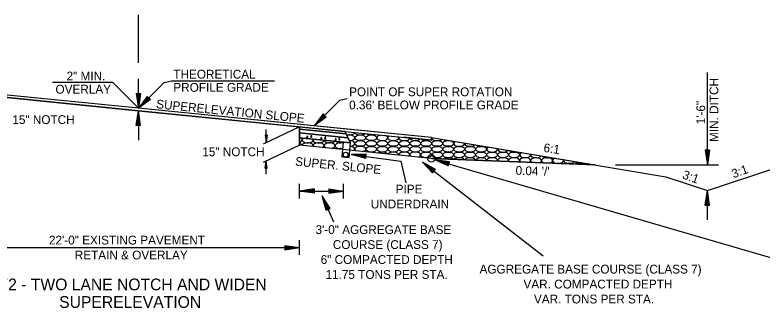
# Model space of a CAD drawing. Extents: x 1371763 to 1372860, y 385599 to 385872.
# Drawn here: x 1372551.5 to 1372602.5, y 385653.6 to 385673.6 of the extents above; entities that cross this region are included whole.
import ezdxf

# ---------------------------------------------------------------- set-up
doc = ezdxf.new("R2010")
doc.units = 0
doc.layers.add('R_Draft', color=7, linetype='Continuous')
doc.layers.add('R_Fin Surface', color=7, linetype='Continuous')

msp = doc.modelspace()

# ---------------------------------------------------------------- linework, layer by layer
at = {"layer": 'R_Draft'}
for p, q in [((1372559.921, 385670.294), (1372559.92, 385673.56)), ((1372598.764, 385663.329), (1372598.764, 385669.627)), ((1372558.173, 385668.943), (1372554.047, 385668.943)), ((1372559.923, 385667.193), (1372558.173, 385668.943)), ((1372559.923, 385667.193), (1372559.923, 385669.193)), ((1372559.923, 385667.193), (1372561.673, 385668.943)), ((1372561.673, 385668.943), (1372562.173, 385669.068)), ((1372562.173, 385669.068), (1372569.212, 385669.068)), ((1372559.923, 385667.026), (1372545.841, 385668.434)), ((1372559.923, 385667.193), (1372547.923, 385668.393)), ((1372559.773, 385668.193), (1372559.923, 385667.193)), ((1372559.773, 385668.193), (1372560.073, 385668.193)), ((1372559.798, 385668.193), (1372559.923, 385667.36)), ((1372559.823, 385668.193), (1372559.923, 385667.532)), ((1372559.848, 385668.193), (1372559.923, 385667.698)), ((1372559.874, 385668.193), (1372559.923, 385667.868)), ((1372559.899, 385668.193), (1372559.923, 385668.035)), ((1372560.073, 385668.193), (1372559.923, 385667.193)), ((1372559.972, 385668.193), (1372559.923, 385667.868)), ((1372560.022, 385668.193), (1372559.923, 385667.532)), ((1372560.048, 385668.193), (1372559.923, 385667.36)), ((1372559.997, 385668.193), (1372559.923, 385667.698)), ((1372559.946, 385668.193), (1372559.923, 385668.035)), ((1372560.524, 385668.006), (1372559.923, 385667.193)), ((1372560.541, 385667.988), (1372560.041, 385667.311)), ((1372560.56, 385667.97), (1372560.162, 385667.432)), ((1372560.577, 385667.952), (1372560.28, 385667.55)), ((1372560.595, 385667.934), (1372560.4, 385667.67)), ((1372560.664, 385667.865), (1372560.4, 385667.67)), ((1372560.613, 385667.916), (1372560.518, 385667.788)), ((1372560.646, 385667.883), (1372560.518, 385667.788)), ((1372560.736, 385667.794), (1372560.524, 385668.006)), ((1372573.673, 385667.743), (1372574.173, 385667.868)), ((1372560.736, 385667.794), (1372559.923, 385667.193)), ((1372560.718, 385667.811), (1372560.041, 385667.311)), ((1372560.7, 385667.829), (1372560.162, 385667.432)), ((1372560.683, 385667.847), (1372560.28, 385667.55)), ((1372571.923, 385665.993), (1372573.673, 385667.743)), ((1372559.773, 385666.026), (1372559.923, 385667.026)), ((1372559.798, 385666.026), (1372559.923, 385666.859)), ((1372571.923, 385665.993), (1372559.923, 385667.193)), ((1372560.073, 385666.026), (1372559.923, 385667.026)), ((1372559.923, 385667.026), (1372559.923, 385665.026)), ((1372560.048, 385666.026), (1372559.923, 385666.859)), ((1372559.823, 385666.026), (1372559.923, 385666.687)), ((1372559.848, 385666.026), (1372559.923, 385666.52)), ((1372559.874, 385666.026), (1372559.923, 385666.351)), ((1372560.022, 385666.026), (1372559.923, 385666.687)), ((1372559.997, 385666.026), (1372559.923, 385666.52)), ((1372559.971, 385666.026), (1372559.923, 385666.351)), ((1372572.524, 385666.806), (1372571.923, 385665.993)), ((1372572.736, 385666.594), (1372571.923, 385665.993)), ((1372572.541, 385666.788), (1372572.041, 385666.111)), ((1372572.718, 385666.611), (1372572.041, 385666.111)), ((1372572.56, 385666.77), (1372572.162, 385666.232)), ((1372572.7, 385666.629), (1372572.162, 385666.232)), ((1372572.577, 385666.752), (1372572.28, 385666.35)), ((1372572.683, 385666.647), (1372572.28, 385666.35)), ((1372572.595, 385666.734), (1372572.4, 385666.47)), ((1372572.664, 385666.665), (1372572.4, 385666.47)), ((1372572.613, 385666.716), (1372572.518, 385666.588)), ((1372572.646, 385666.683), (1372572.518, 385666.588)), ((1372572.736, 385666.594), (1372572.524, 385666.806)), ((1372560.073, 385666.026), (1372559.773, 385666.026)), ((1372559.899, 385666.026), (1372559.923, 385666.184)), ((1372559.946, 385666.026), (1372559.923, 385666.184)), ((1372570.921, 385665.926), (1372568.433, 385664.754)), ((1372579.918, 385665.193), (1372571.923, 385665.993)), ((1372568.571, 385665.354), (1372568.646, 385664.854)), ((1372568.721, 385665.354), (1372568.571, 385665.354)), ((1372568.583, 385665.354), (1372568.646, 385664.938)), ((1372568.596, 385665.354), (1372568.646, 385665.024)), ((1372568.609, 385665.354), (1372568.646, 385665.107)), ((1372568.621, 385665.354), (1372568.646, 385665.192)), ((1372568.634, 385665.354), (1372568.646, 385665.275)), ((1372568.646, 385664.854), (1372568.646, 385665.754)), ((1372568.721, 385665.354), (1372568.646, 385664.854)), ((1372568.67, 385665.354), (1372568.646, 385665.192)), ((1372568.696, 385665.354), (1372568.646, 385665.024)), ((1372568.708, 385665.354), (1372568.646, 385664.938)), ((1372568.683, 385665.354), (1372568.646, 385665.107)), ((1372568.658, 385665.354), (1372568.646, 385665.275)), ((1372574.096, 385665.442), (1372570.922, 385665.759)), ((1372574.228, 385665.179), (1372570.922, 385665.509)), ((1372574.009, 385665.617), (1372574.403, 385664.828)), ((1372574.403, 385664.828), (1372570.922, 385665.176)), ((1372579.918, 385665.026), (1372578.01, 385665.217)), ((1372579.918, 385665.193), (1372595.918, 385662.526)), ((1372579.918, 385665.193), (1372579.918, 385665.026)), ((1372570.921, 385664.676), (1372568.434, 385663.504)), ((1372579.918, 385663.776), (1372570.921, 385664.676)), ((1372598.614, 385664.329), (1372598.764, 385663.329)), ((1372598.914, 385664.329), (1372598.614, 385664.329)), ((1372598.639, 385664.329), (1372598.764, 385663.496)), ((1372598.665, 385664.329), (1372598.764, 385663.668)), ((1372598.69, 385664.329), (1372598.764, 385663.835)), ((1372598.715, 385664.329), (1372598.764, 385664.004)), ((1372598.741, 385664.329), (1372598.764, 385664.171)), ((1372598.914, 385664.329), (1372598.764, 385663.329)), ((1372598.813, 385664.329), (1372598.764, 385664.004)), ((1372598.864, 385664.329), (1372598.764, 385663.668)), ((1372598.889, 385664.329), (1372598.764, 385663.496)), ((1372598.839, 385664.329), (1372598.764, 385663.835)), ((1372598.788, 385664.329), (1372598.764, 385664.171)), ((1372575.478, 385664.057), (1372574.466, 385664.042)), ((1372574.466, 385664.042), (1372577.831, 385663.586)), ((1372575.437, 385663.759), (1372574.466, 385664.042)), ((1372575.474, 385664.032), (1372574.632, 385664.02)), ((1372575.441, 385663.784), (1372574.632, 385664.02)), ((1372575.471, 385664.007), (1372574.802, 385663.997)), ((1372575.444, 385663.809), (1372574.802, 385663.997)), ((1372575.467, 385663.982), (1372574.967, 385663.974)), ((1372575.447, 385663.834), (1372574.967, 385663.974)), ((1372575.464, 385663.957), (1372575.135, 385663.952)), ((1372575.451, 385663.86), (1372575.135, 385663.952)), ((1372575.461, 385663.931), (1372575.301, 385663.929)), ((1372575.454, 385663.885), (1372575.301, 385663.929)), ((1372575.437, 385663.759), (1372575.478, 385664.057)), ((1372579.918, 385663.776), (1372591.103, 385663.329)), ((1372579.918, 385663.776), (1372591.103, 385663.329)), ((1372568.571, 385663.104), (1372568.646, 385663.604)), ((1372568.584, 385663.104), (1372568.646, 385663.521)), ((1372568.597, 385663.104), (1372568.646, 385663.435)), ((1372568.609, 385663.104), (1372568.646, 385663.352)), ((1372568.622, 385663.104), (1372568.646, 385663.267)), ((1372568.721, 385663.104), (1372568.646, 385663.604)), ((1372568.646, 385662.704), (1372568.646, 385663.604)), ((1372568.709, 385663.104), (1372568.646, 385663.521)), ((1372568.696, 385663.104), (1372568.646, 385663.435)), ((1372568.684, 385663.104), (1372568.646, 385663.352)), ((1372568.671, 385663.104), (1372568.646, 385663.267)), ((1372577.831, 385663.586), (1372578.171, 385662.109)), ((1372580.007, 385662.782), (1372579.308, 385663.513)), ((1372580.191, 385663.019), (1372579.308, 385663.513)), ((1372579.308, 385663.513), (1372587.56, 385657.125)), ((1372580.022, 385662.802), (1372579.44, 385663.411)), ((1372580.175, 385663), (1372579.44, 385663.411)), ((1372580.16, 385662.979), (1372579.576, 385663.305)), ((1372580.038, 385662.822), (1372579.576, 385663.305)), ((1372581.069, 385663.261), (1372580.151, 385663.684)), ((1372581.153, 385663.549), (1372580.151, 385663.684)), ((1372580.151, 385663.684), (1372603.456, 385656.902)), ((1372581.076, 385663.285), (1372580.311, 385663.638)), ((1372581.146, 385663.525), (1372580.311, 385663.638)), ((1372581.139, 385663.5), (1372580.476, 385663.59)), ((1372581.083, 385663.309), (1372580.476, 385663.59)), ((1372581.09, 385663.333), (1372580.636, 385663.543)), ((1372581.132, 385663.476), (1372580.636, 385663.543)), ((1372581.125, 385663.452), (1372580.799, 385663.496)), ((1372581.097, 385663.358), (1372580.799, 385663.496)), ((1372581.118, 385663.428), (1372580.959, 385663.449)), ((1372581.104, 385663.382), (1372580.959, 385663.449)), ((1372581.069, 385663.261), (1372581.153, 385663.549)), ((1372592.486, 385663.329), (1372599.514, 385663.329)), ((1372568.571, 385663.104), (1372568.721, 385663.104)), ((1372568.635, 385663.104), (1372568.646, 385663.183)), ((1372568.658, 385663.104), (1372568.646, 385663.183)), ((1372580.053, 385662.842), (1372579.708, 385663.203)), ((1372580.145, 385662.96), (1372579.708, 385663.203)), ((1372580.129, 385662.94), (1372579.842, 385663.1)), ((1372580.069, 385662.862), (1372579.842, 385663.1)), ((1372580.113, 385662.919), (1372579.974, 385662.998)), ((1372580.085, 385662.882), (1372579.974, 385662.998)), ((1372580.007, 385662.782), (1372580.191, 385663.019)), ((1372570.923, 385661.044), (1372570.923, 385662.044)), ((1372573.923, 385661.044), (1372573.923, 385662.044)), ((1372571.923, 385661.694), (1372570.923, 385661.544)), ((1372571.923, 385661.394), (1372570.923, 385661.544)), ((1372570.923, 385661.544), (1372573.923, 385661.544)), ((1372571.923, 385661.669), (1372571.09, 385661.544)), ((1372571.923, 385661.419), (1372571.09, 385661.544)), ((1372571.923, 385661.644), (1372571.262, 385661.544)), ((1372571.923, 385661.445), (1372571.262, 385661.544)), ((1372571.923, 385661.619), (1372571.428, 385661.544)), ((1372571.923, 385661.47), (1372571.428, 385661.544)), ((1372571.923, 385661.593), (1372571.598, 385661.544)), ((1372571.923, 385661.495), (1372571.598, 385661.544)), ((1372571.923, 385661.568), (1372571.765, 385661.544)), ((1372571.923, 385661.521), (1372571.765, 385661.544)), ((1372571.923, 385661.694), (1372571.923, 385661.394)), ((1372572.923, 385661.694), (1372573.923, 385661.544)), ((1372572.923, 385661.694), (1372572.923, 385661.394)), ((1372572.923, 385661.669), (1372573.756, 385661.544)), ((1372572.923, 385661.644), (1372573.584, 385661.544)), ((1372572.923, 385661.619), (1372573.417, 385661.544)), ((1372572.923, 385661.593), (1372573.248, 385661.544)), ((1372572.923, 385661.568), (1372573.081, 385661.544)), ((1372572.923, 385661.394), (1372573.923, 385661.544)), ((1372572.923, 385661.495), (1372573.248, 385661.544)), ((1372572.923, 385661.445), (1372573.584, 385661.544)), ((1372572.923, 385661.419), (1372573.756, 385661.544)), ((1372572.923, 385661.47), (1372573.417, 385661.544)), ((1372572.923, 385661.521), (1372573.081, 385661.544)), ((1372598.614, 385660.578), (1372598.764, 385661.578)), ((1372598.639, 385660.578), (1372598.764, 385661.411)), ((1372598.665, 385660.578), (1372598.764, 385661.239)), ((1372598.914, 385660.578), (1372598.764, 385661.578)), ((1372598.764, 385659.578), (1372598.764, 385661.578)), ((1372598.889, 385660.578), (1372598.764, 385661.411)), ((1372598.864, 385660.578), (1372598.764, 385661.239)), ((1372572.733, 385660.236), (1372572.468, 385661.212)), ((1372573.007, 385660.356), (1372572.468, 385661.212)), ((1372572.468, 385661.212), (1372573.247, 385659.438)), ((1372572.756, 385660.246), (1372572.535, 385661.059)), ((1372572.984, 385660.346), (1372572.535, 385661.059)), ((1372572.961, 385660.336), (1372572.604, 385660.901)), ((1372572.779, 385660.256), (1372572.604, 385660.901)), ((1372572.802, 385660.266), (1372572.671, 385660.749)), ((1372572.938, 385660.326), (1372572.671, 385660.749)), ((1372598.69, 385660.578), (1372598.764, 385661.072)), ((1372598.716, 385660.578), (1372598.764, 385660.903)), ((1372598.741, 385660.578), (1372598.764, 385660.736)), ((1372598.839, 385660.578), (1372598.764, 385661.072)), ((1372598.813, 385660.578), (1372598.764, 385660.903)), ((1372598.788, 385660.578), (1372598.764, 385660.736)), ((1372572.733, 385660.236), (1372573.007, 385660.356)), ((1372572.915, 385660.316), (1372572.739, 385660.594)), ((1372572.826, 385660.277), (1372572.739, 385660.594)), ((1372572.891, 385660.306), (1372572.806, 385660.441)), ((1372572.848, 385660.287), (1372572.806, 385660.441)), ((1372598.614, 385660.578), (1372598.914, 385660.578)), ((1372570.921, 385657.191), (1372570.921, 385658.191)), ((1372548.921, 385657.691), (1372570.921, 385657.691)), ((1372569.921, 385657.841), (1372570.921, 385657.691)), ((1372569.921, 385657.841), (1372569.921, 385657.541)), ((1372569.921, 385657.816), (1372570.754, 385657.691)), ((1372569.921, 385657.79), (1372570.582, 385657.691)), ((1372569.921, 385657.765), (1372570.415, 385657.691)), ((1372569.921, 385657.739), (1372570.246, 385657.691)), ((1372569.921, 385657.714), (1372570.079, 385657.691)), ((1372569.921, 385657.541), (1372570.921, 385657.691)), ((1372569.921, 385657.642), (1372570.246, 385657.691)), ((1372569.921, 385657.591), (1372570.582, 385657.691)), ((1372569.921, 385657.566), (1372570.754, 385657.691)), ((1372569.921, 385657.616), (1372570.415, 385657.691)), ((1372569.921, 385657.667), (1372570.079, 385657.691))]:
    msp.add_line(p, q, dxfattribs=at)
for points in [[(1372559.923, 385667.193), (1372545.92, 385668.593), (1372539.919, 385669.193), (1372539.919, 385669.026), (1372545.841, 385668.434), (1372548.921, 385668.126), (1372559.923, 385667.026), (1372570.921, 385665.926), (1372574.009, 385665.617), (1372579.918, 385665.026), (1372579.92, 385665.193), (1372573.921, 385665.793)], [(1372570.921, 385665.926), (1372574.009, 385665.617), (1372574.096, 385665.442), (1372570.922, 385665.759)], [(1372579.918, 385663.776), (1372570.921, 385664.676), (1372570.922, 385665.176), (1372574.403, 385664.828), (1372574.228, 385665.179), (1372574.096, 385665.442), (1372574.009, 385665.617), (1372579.918, 385665.026), (1372579.918, 385665.193), (1372591.103, 385663.329)], [(1372570.922, 385665.509), (1372570.922, 385665.759), (1372574.096, 385665.442), (1372574.228, 385665.179)], [(1372570.922, 385665.509), (1372574.228, 385665.179), (1372574.403, 385664.828), (1372570.922, 385665.176)], [(1372573.902, 385664.878), (1372573.803, 385663.885), (1372574.304, 385663.835), (1372574.403, 385664.828)]]:
    msp.add_lwpolyline(points, close=True, dxfattribs=at)
for points in [[(1372574.009, 385665.617), (1372559.923, 385667.026)], [(1372570.921, 385665.926), (1372570.922, 385665.759), (1372570.922, 385665.509), (1372570.922, 385665.176), (1372570.921, 385664.676)], [(1372571.461, 385665.324), (1372571.398, 385665.198), (1372571.486, 385665.192), (1372571.461, 385665.324)], [(1372571.726, 385665.361), (1372571.663, 385665.234), (1372571.751, 385665.228), (1372571.726, 385665.361)], [(1372572.425, 385665.228), (1372572.362, 385665.101), (1372572.45, 385665.095), (1372572.425, 385665.228)], [(1372572.69, 385665.264), (1372572.627, 385665.138), (1372572.715, 385665.131), (1372572.69, 385665.264)], [(1372573.389, 385665.132), (1372573.326, 385665.005), (1372573.414, 385664.999), (1372573.389, 385665.132)], [(1372573.654, 385665.168), (1372573.591, 385665.041), (1372573.679, 385665.035), (1372573.654, 385665.168)]]:
    msp.add_lwpolyline(points, dxfattribs=at)
for centre, radius in [((1372574.07, 385664.026), 0.167), ((1372579.918, 385663.776), 0.25)]:
    msp.add_circle(centre, radius, dxfattribs=at)
for centre, start_param, end_param in [((1372574.315, 385665.568), 4.151582, 6.188458), ((1372574.315, 385665.179), 1.184818, 2.051954), ((1372574.315, 385665.179), 4.73799, 7.468004), ((1372575.065, 385665.568), 3.238092, 5.805198), ((1372575.816, 385665.568), 3.674985, 5.368305), ((1372576.566, 385665.179), 1.777481, 7.265809), ((1372577.316, 385665.179), 2.376985, 6.666305), ((1372570.719, 385664.637), 0.116474, 0.999932), ((1372570.719, 385665.025), 5.283453, 7.139386), ((1372571.469, 385665.025), 2.442518, 6.600772), ((1372571.469, 385664.637), 6.015594, 9.310881), ((1372572.219, 385664.637), 5.619002, 9.707473), ((1372572.219, 385665.025), 2.843099, 6.200191), ((1372572.97, 385664.637), 5.104074, 10.222401), ((1372572.97, 385665.025), 3.225943, 5.817347), ((1372573.72, 385664.637), 1.083587, 5.096112), ((1372573.72, 385665.025), 3.659508, 5.213681), ((1372574.315, 385664.791), 0.245719, 1.545025), ((1372574.315, 385664.791), 4.887187, 6.528905), ((1372578.067, 385665.179), 2.786407, 6.256883), ((1372578.817, 385665.179), 3.168029, 5.875261), ((1372579.567, 385665.179), 3.587687, 5.455603), ((1372579.567, 385665.179), 5.930026, 6.335044), ((1372580.317, 385665.179), 3.090586, 5.711462), ((1372581.068, 385665.179), 3.885721, 4.916327), ((1372581.818, 385664.791), 2.395711, 6.326095), ((1372582.568, 385664.791), 3.023167, 5.778882), ((1372581.818, 385664.791), 0.04291, 0.123152), ((1372573.72, 385664.248), 1.195019, 2.103665), ((1372574.315, 385664.402), 0.934459, 1.397587), ((1372574.315, 385664.402), 5.755866, 7.217645), ((1372575.065, 385664.402), 5.303745, 10.02273), ((1372583.318, 385664.791), 3.764994, 5.037054), ((1372584.069, 385664.402), 2.32197, 6.480078), ((1372584.819, 385664.402), 2.956625, 5.845423), ((1372585.569, 385664.402), 3.661482, 5.140566), ((1372575.816, 385664.014), 0.874925, 1.88518), ((1372576.566, 385664.014), 0.328166, 2.431939), ((1372577.316, 385664.014), 6.209463, 9.117012), ((1372578.067, 385664.014), 5.826908, 9.499567), ((1372578.817, 385664.014), 5.395855, 9.93062), ((1372579.567, 385663.625), 1.040624, 1.719481), ((1372580.317, 385663.625), 0.691764, 2.295662), ((1372581.068, 385663.625), 0.49489, 2.492535), ((1372581.818, 385663.625), 0.320594, 2.666831), ((1372582.568, 385663.625), 0.158349, 2.829076), ((1372583.318, 385663.625), 0.002249, 2.985176), ((1372584.069, 385663.625), 6.131267, 9.422529), ((1372584.819, 385663.625), 5.975278, 9.578518), ((1372585.569, 385663.625), 5.813283, 9.740513), ((1372586.319, 385664.014), 2.245061, 6.556988), ((1372586.319, 385663.625), 5.639452, 9.914344), ((1372587.07, 385663.625), 5.443475, 10.110321), ((1372587.07, 385664.014), 2.890642, 5.911406), ((1372587.82, 385663.625), 5.199841, 10.353956), ((1372587.82, 385664.014), 3.568612, 5.233436), ((1372588.57, 385663.625), 2.164004, 4.587381), ((1372588.57, 385663.625), 4.68323, 6.638044), ((1372588.57, 385663.236), 1.395788, 1.591637), ((1372589.321, 385663.625), 2.824922, 5.977126), ((1372589.321, 385663.236), 0.922405, 2.06502), ((1372590.071, 385663.625), 3.483025, 5.319023), ((1372590.071, 385663.236), 0.680517, 2.306909), ((1372590.821, 385663.236), 2.0774, 2.502171)]:
    msp.add_ellipse(centre, major_axis=(0.375, 0), ratio=0.517889, start_param=start_param, end_param=end_param, dxfattribs=at)
for centre in [(1372575.065, 385665.179), (1372575.816, 385665.179), (1372575.065, 385664.791), (1372575.816, 385664.791), (1372576.566, 385664.791), (1372577.316, 385664.791), (1372578.067, 385664.791), (1372578.817, 385664.791), (1372579.567, 385664.791), (1372580.317, 385664.791), (1372581.068, 385664.791), (1372575.816, 385664.402), (1372576.566, 385664.402), (1372577.316, 385664.402), (1372578.067, 385664.402), (1372578.817, 385664.402), (1372579.567, 385664.402), (1372580.317, 385664.402), (1372581.068, 385664.402), (1372581.818, 385664.402), (1372582.568, 385664.402), (1372583.318, 385664.402), (1372579.567, 385664.014), (1372580.317, 385664.014), (1372581.068, 385664.014), (1372581.818, 385664.014), (1372582.568, 385664.014), (1372583.318, 385664.014), (1372584.069, 385664.014), (1372584.819, 385664.014), (1372585.569, 385664.014)]:
    msp.add_ellipse(centre, major_axis=(0.375, 0), ratio=0.517889, dxfattribs=at)
at = {"layer": 'R_Fin Surface'}
for p, q in [((1372598.764, 385661.578), (1372603.508, 385663.159)), ((1372595.918, 385662.526), (1372598.764, 385661.578))]:
    msp.add_line(p, q, dxfattribs=at)

# ---------------------------------------------------------------- texts
at = {"layer": 'R_Draft'}
for s, height, p in [('2" MIN.', 0.6, (1372555.016, 385669.093)), ('THEORETICAL', 0.6, (1372562.306, 385669.218)), ('PROFILE GRADE', 0.6, (1372562.306, 385668.318)), ('OVERLAY', 0.6, (1372554.26, 385668.193)), ('POINT OF SUPER ROTATION', 0.6, (1372574.306, 385668.018)), ("0.36' BELOW PROFILE GRADE", 0.6, (1372574.306, 385667.118)), ('15" NOTCH', 0.6, (1372551.316, 385666.118)), ('15" NOTCH', 0.6, (1372564.28, 385663.924)), ('HWY. 72 - TWO LANE NOTCH AND WIDEN', 0.8, (1372547.344, 385654.775)), ('SUPERELEVATION', 0.8, (1372554.512, 385653.575))]:
    msp.add_text(s, height=height, dxfattribs=at).set_placement(p)
for s, rotation, p in [('MIN. DITCH', 90, (1372599.508, 385664.892)), ('SUPERELEVATION SLOPE', 354.3792, (1372561.114, 385667.197)), ('1\'-6"', 90, (1372598.608, 385666.099)), ('6:1', 352.2846, (1372587.548, 385664.217)), ('SUPER. SLOPE', 354.3792, (1372570.601, 385663.282)), ("0.04 '/'", 358.17, (1372585.661, 385662.658)), ('3:1', 19.9978, (1372600.547, 385662.411)), ('3:1', 340.0022, (1372597.007, 385662.424)), ('PIPE', 0, (1372577.484, 385661.38)), ('UNDERDRAIN', 0, (1372575.781, 385660.36)), ('3\'-0" AGGREGATE BASE ', 360, (1372572.011, 385658.612)), ('22\'-0" EXISTING PAVEMENT', 360, (1372553.815, 385657.901)), ('COURSE (CLASS 7)', 360, (1372573.193, 385657.592)), ('RETAIN & OVERLAY', 360, (1372555.574, 385656.881)), ('6" COMPACTED DEPTH', 360, (1372572.361, 385656.572)), ('11.75 TONS PER STA.', 360, (1372572.696, 385655.552)), ('AGGREGATE BASE COURSE (CLASS 7)', 360, (1372583.209, 385655.918)), ('VAR. COMPACTED DEPTH', 360, (1372586.209, 385654.898)), ('VAR. TONS PER STA.', 360, (1372586.922, 385653.878))]:
    msp.add_text(s, height=0.6, rotation=rotation, dxfattribs=at).set_placement(p)

doc.saveas('drawing.dxf')
